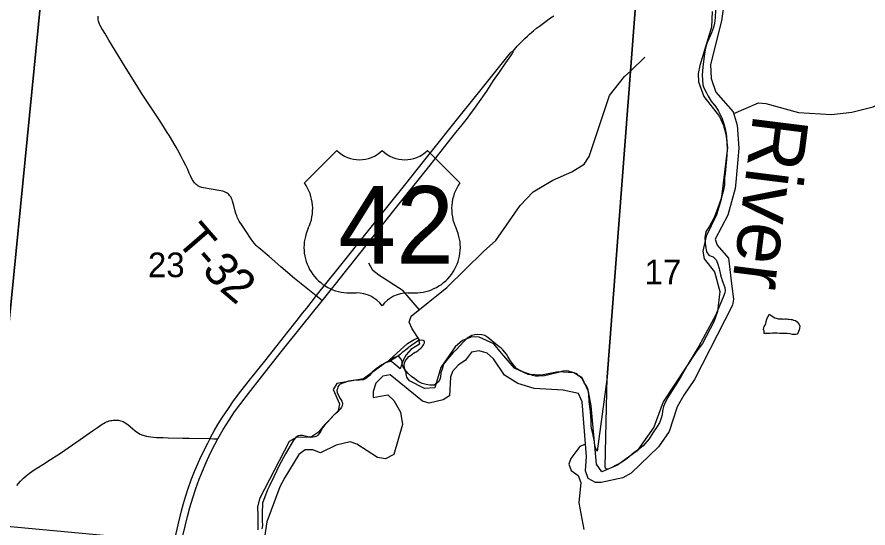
# Model space of a CAD drawing. Extents: x -19.5 to 44.1, y 0 to 22.
# Drawn here: x -17.865 to -16.421, y 14.832 to 15.7 of the extents above; entities that cross this region are included whole.
import ezdxf

# ---------------------------------------------------------------- set-up
doc = ezdxf.new("R2010")
doc.units = 0
for name, color, linetype in [('GM_X_Major_River', 7, 'Continuous'), ('GM_X_Major_River_Text', 7, 'Continuous'), ('GM_X_Minor_Lake', 7, 'Continuous'), ('GM_X_Minor_River', 7, 'Continuous'), ('GM_X_Section', 7, 'Continuous'), ('GM_X_Section_Text', 7, 'Continuous'), ('GM_X_Township_Road', 7, 'Continuous'), ('GM_X_Township_Road_Text', 7, 'Continuous'), ('GM_X_US_Location', 7, 'Continuous'), ('GM_X_US_Route', 7, 'Continuous'), ('GM_X_US_Shield', 7, 'Continuous')]:
    doc.layers.add(name, color=color, linetype=linetype)

msp = doc.modelspace()

# ---------------------------------------------------------------- linework, layer by layer
at = {"layer": 'GM_X_Major_River'}
for points in [[(-16.6661, 15.717), (-16.6691, 15.6932), (-16.6878, 15.6192), (-16.6867, 15.5953), (-16.6787, 15.5718), (-16.6493, 15.5389), (-16.6425, 15.5159), (-16.6399, 15.4767), (-16.6452, 15.4194), (-16.6463, 15.4084), (-16.6584, 15.3632), (-16.6798, 15.3224), (-16.6767, 15.3124), (-16.6573, 15.2898), (-16.652, 15.2421), (-16.6489, 15.2203), (-16.6508, 15.2105), (-16.7152, 15.084)], [(-16.6853, 15.7093), (-16.6862, 15.6823), (-16.7061, 15.6175), (-16.7088, 15.6036), (-16.7081, 15.5895), (-16.6991, 15.5649), (-16.6728, 15.5306), (-16.6657, 15.5155), (-16.662, 15.5006), (-16.6589, 15.478), (-16.6701, 15.3898), (-16.6778, 15.3638), (-16.6956, 15.3275), (-16.701, 15.3022), (-16.6988, 15.2892), (-16.6813, 15.2666), (-16.6724, 15.2336), (-16.6762, 15.1995), (-16.6821, 15.1822), (-16.7015, 15.1452), (-16.711, 15.1325), (-16.7681, 15.0461), (-16.7839, 15.0033), (-16.8126, 14.9631), (-16.8456, 14.9383), (-16.8722, 14.927), (-16.8813, 14.9402), (-16.8903, 15.0394), (-16.8948, 15.0635)], [(-17.2033, 15.0879), (-17.2042, 15.0936), (-17.2046, 15.0966), (-17.206, 15.0993), (-17.2071, 15.1046), (-17.2079, 15.1077), (-17.207, 15.1119), (-17.2059, 15.1149), (-17.2047, 15.1172), (-17.202, 15.1202), (-17.2001, 15.1228), (-17.197, 15.125), (-17.1939, 15.1269), (-17.192, 15.1288), (-17.1893, 15.1303), (-17.1874, 15.131), (-17.1848, 15.1325), (-17.1825, 15.1347), (-17.1794, 15.137), (-17.1775, 15.1392), (-17.1748, 15.143), (-17.1732, 15.146), (-17.1732, 15.1483), (-17.1754, 15.1502), (-17.1785, 15.1507), (-17.1815, 15.1503), (-17.1838, 15.1496), (-17.1869, 15.1477), (-17.1896, 15.1459), (-17.1915, 15.1444), (-17.1941, 15.1429), (-17.1976, 15.1403), (-17.201, 15.1384), (-17.2026, 15.1361), (-17.2049, 15.1343), (-17.208, 15.1324), (-17.211, 15.1298), (-17.2145, 15.1264), (-17.2168, 15.1249), (-17.2191, 15.1234), (-17.221, 15.1219), (-17.2237, 15.1201), (-17.2264, 15.1186), (-17.2298, 15.1163), (-17.2317, 15.1145), (-17.2398, 15.1121)], [(-17.2328, 15.1172), (-17.2024, 15.1451), (-17.1909, 15.152), (-17.184, 15.1549), (-17.1816, 15.1439), (-17.1966, 15.1351), (-17.2043, 15.1261), (-17.209, 15.1182), (-17.2144, 15.1021)], [(-16.8948, 15.0635), (-16.9055, 15.0866), (-16.9197, 15.0951), (-16.9466, 15.0971), (-16.9749, 15.0911), (-16.9976, 15.0926), (-17.0205, 15.1032), (-17.0425, 15.1286), (-17.0556, 15.1443), (-17.0803, 15.1561), (-17.0932, 15.1565), (-17.1086, 15.1501), (-17.1215, 15.1395), (-17.1458, 15.1042), (-17.1557, 15.0699), (-17.1732, 15.0689), (-17.1986, 15.0819), (-17.2033, 15.0879)], [(-16.7152, 15.084), (-16.7332, 15.0572), (-16.7448, 15.0374), (-16.7583, 14.9956), (-16.7763, 14.9696), (-16.8225, 14.9247), (-16.8365, 14.9168), (-16.8736, 14.9088), (-16.8831, 14.9091), (-16.8954, 14.9156), (-16.9003, 14.929), (-16.8984, 14.9533), (-16.9057, 15.0459), (-16.912, 15.0602), (-16.9381, 15.0656), (-16.9874, 15.0687), (-17.0148, 15.0772), (-17.0376, 15.0912), (-17.0561, 15.1192), (-17.0671, 15.129), (-17.0807, 15.1325), (-17.0933, 15.1306), (-17.104, 15.1169), (-17.1164, 15.1082), (-17.1259, 15.0978), (-17.1292, 15.088), (-17.131, 15.0565), (-17.1419, 15.0497), (-17.1652, 15.0436), (-17.1769, 15.0473), (-17.2317, 15.0917), (-17.2443, 15.0898), (-17.2557, 15.0776), (-17.2603, 15.0637), (-17.2603, 15.0534), (-17.2355, 15.058), (-17.2255, 15.0485), (-17.214, 15.0287), (-17.2105, 15.0073), (-17.2254, 14.9565), (-17.2397, 14.9493), (-17.2533, 14.9517), (-17.2883, 14.9741), (-17.2996, 14.9779), (-17.3233, 14.9725), (-17.3496, 14.9593), (-17.3627, 14.9643), (-17.3756, 14.9643), (-17.3865, 14.9567), (-17.4106, 14.9175), (-17.4187, 14.9018), (-17.4411, 14.842), (-17.4478, 14.7978)], [(-17.2398, 15.1121), (-17.2771, 15.0851), (-17.3222, 15.0771), (-17.3283, 15.067), (-17.3176, 15.0427), (-17.3199, 15.031), (-17.3427, 15.0074), (-17.3534, 14.9944), (-17.367, 14.9857), (-17.3901, 14.9861), (-17.4029, 14.9789), (-17.4531, 14.8812), (-17.4566, 14.8673), (-17.4559, 14.8532), (-17.456, 14.8284)], [(-17.2144, 15.1021), (-17.2328, 15.1172)]]:
    msp.add_lwpolyline(points, dxfattribs=at)
at = {"layer": 'GM_X_Minor_Lake'}
msp.add_lwpolyline([(-16.5881, 15.1948), (-16.5865, 15.1938), (-16.5838, 15.1922), (-16.5819, 15.1907), (-16.5789, 15.1888), (-16.5763, 15.188), (-16.5732, 15.1872), (-16.5694, 15.1871), (-16.566, 15.1871), (-16.5641, 15.1867), (-16.5618, 15.187), (-16.5592, 15.187), (-16.5565, 15.1866), (-16.5542, 15.1865), (-16.5512, 15.1857), (-16.5493, 15.1857), (-16.547, 15.1846), (-16.544, 15.1841), (-16.541, 15.1822), (-16.5376, 15.1776), (-16.5365, 15.1745), (-16.5369, 15.1711), (-16.5377, 15.1685), (-16.5389, 15.1658), (-16.5397, 15.1628), (-16.5405, 15.1609), (-16.5424, 15.1602), (-16.5443, 15.1602), (-16.5462, 15.1602), (-16.5488, 15.1606), (-16.5526, 15.1614), (-16.5576, 15.1619), (-16.5648, 15.162), (-16.5705, 15.1624), (-16.575, 15.1629), (-16.5785, 15.1625), (-16.5804, 15.1625), (-16.583, 15.1626), (-16.5865, 15.1622), (-16.5895, 15.1623), (-16.5918, 15.1623), (-16.5937, 15.162), (-16.5971, 15.162), (-16.597, 15.1662), (-16.5978, 15.1688), (-16.5977, 15.1719), (-16.597, 15.1738), (-16.5954, 15.176), (-16.5939, 15.1791), (-16.5934, 15.1825), (-16.5923, 15.1863), (-16.5883, 15.1949)], dxfattribs=at)
at = {"layer": 'GM_X_Minor_River'}
for points in [[(-17.1814, 15.1503), (-17.194, 15.1703), (-17.1991, 15.1815), (-17.1962, 15.1917), (-17.1357, 15.2401), (-17.0734, 15.3015), (-17.0522, 15.32), (-17.0108, 15.3796), (-16.9887, 15.4027), (-16.9557, 15.4228), (-16.9231, 15.4366), (-16.9024, 15.4498), (-16.8938, 15.4626), (-16.8591, 15.5663), (-16.8342, 15.5988), (-16.8234, 15.6081), (-16.7994, 15.6315)], [(-16.6485, 15.5359), (-16.6063, 15.5537), (-16.5938, 15.5526), (-16.5387, 15.5374), (-16.4829, 15.5343), (-16.4483, 15.5381), (-16.4121, 15.5472), (-16.3125, 15.5949), (-16.3029, 15.5992), (-16.1433, 15.5563), (-16.1041, 15.5433), (-16.0813, 15.5436), (-16.0065, 15.5818), (-15.9738, 15.5891), (-15.9377, 15.6089)], [(-17.1825, 15.2027), (-17.2094, 15.2345), (-17.251, 15.2612), (-17.2611, 15.2694), (-17.2677, 15.2814)], [(-16.9, 14.9744), (-16.9099, 14.9701), (-16.9251, 14.9499), (-16.9283, 14.9401), (-16.9243, 14.9297), (-16.9127, 14.9211), (-16.908, 14.9093), (-16.9114, 14.8747), (-16.9031, 14.8294)]]:
    msp.add_lwpolyline(points, dxfattribs=at)
at = {"layer": 'GM_X_Section'}
msp.add_lwpolyline([(-18.8417, 15.9351), (-17.8129, 15.843), (-17.9125, 14.8374), (-18.924, 14.9235)], close=True, dxfattribs=at)
for points in [[(-17.5783, 14.8063), (-17.9125, 14.8374), (-17.8129, 15.843)], [(-16.8129, 15.7495), (-16.8634, 15.0877), (-16.8804, 14.9623), (-16.8826, 14.9665), (-16.884, 14.9718), (-16.885, 14.9779), (-16.8857, 14.9836), (-16.8864, 14.9862), (-16.8878, 14.9923), (-16.8892, 14.9984), (-16.8903, 15.0045), (-16.8905, 15.014), (-16.8917, 15.0303), (-16.8941, 15.0462), (-16.8946, 15.0587), (-16.8956, 15.0659), (-16.8967, 15.0697), (-16.8985, 15.0732), (-16.9004, 15.0762), (-16.9022, 15.0782), (-16.9033, 15.0808), (-16.9052, 15.0846), (-16.9096, 15.0893), (-16.9119, 15.0904), (-16.9137, 15.0924), (-16.9163, 15.0943), (-16.9194, 15.0955), (-16.9258, 15.0971), (-16.9291, 15.0983), (-16.9322, 15.0987), (-16.9386, 15.0981), (-16.9489, 15.0956), (-16.9626, 15.0917), (-16.9698, 15.0903), (-16.9797, 15.0897), (-16.985, 15.0898), (-16.9899, 15.091), (-16.9932, 15.0926), (-17, 15.0946), (-17.0064, 15.097), (-17.012, 15.1001), (-17.0173, 15.1029), (-17.0206, 15.1067), (-17.0243, 15.1117), (-17.0284, 15.1175), (-17.0317, 15.1232), (-17.0339, 15.127), (-17.0402, 15.1343), (-17.0432, 15.137), (-17.0466, 15.1397), (-17.0526, 15.1444), (-17.0593, 15.1494), (-17.066, 15.1552), (-17.0709, 15.1587), (-17.0761, 15.1599), (-17.0829, 15.1604), (-17.0879, 15.1601), (-17.0932, 15.1587), (-17.1016, 15.1539), (-17.1066, 15.1483), (-17.1132, 15.1409), (-17.119, 15.1349), (-17.1248, 15.1301), (-17.1344, 15.1185), (-17.141, 15.1099), (-17.1434, 15.1017), (-17.1454, 15.0956), (-17.1459, 15.0881), (-17.1471, 15.0839), (-17.1495, 15.0802), (-17.1545, 15.0761), (-17.1571, 15.0746), (-17.1598, 15.0743), (-17.164, 15.0744), (-17.1704, 15.0756), (-17.1775, 15.0773), (-17.1843, 15.0804), (-17.1899, 15.085), (-17.1955, 15.0889), (-17.2011, 15.0943), (-17.2067, 15.1012), (-17.21, 15.1066), (-17.2111, 15.1096), (-17.2113, 15.1153), (-17.2135, 15.1192), (-17.2158, 15.1218), (-17.2188, 15.1234), (-17.2245, 15.1212), (-17.2337, 15.1157), (-17.2459, 15.1087), (-17.2555, 15.1021), (-17.262, 15.0965), (-17.2667, 15.0909), (-17.2713, 15.0868), (-17.2744, 15.0846), (-17.2774, 15.0835), (-17.2839, 15.0829), (-17.2945, 15.0823), (-17.3021, 15.0813), (-17.3104, 15.0784), (-17.3165, 15.0759), (-17.3188, 15.074), (-17.3204, 15.0714), (-17.3212, 15.0684), (-17.322, 15.0657), (-17.3213, 15.062), (-17.3199, 15.0581), (-17.3166, 15.052), (-17.3136, 15.0474), (-17.3126, 15.044), (-17.313, 15.0395), (-17.3142, 15.0372), (-17.3165, 15.0335), (-17.3211, 15.0286), (-17.3269, 15.0238), (-17.3385, 15.0107), (-17.3435, 15.0052), (-17.347, 15.0011), (-17.3494, 14.9962), (-17.3521, 14.9921), (-17.3544, 14.9894), (-17.3563, 14.9876), (-17.3597, 14.9865), (-17.3624, 14.9862), (-17.3692, 14.9863), (-17.3756, 14.9879), (-17.3802, 14.9888), (-17.3843, 14.9888), (-17.3877, 14.9881), (-17.3916, 14.9855), (-17.3954, 14.9807), (-17.4036, 14.9676), (-17.4095, 14.9578), (-17.4197, 14.9379), (-17.4291, 14.9188), (-17.4362, 14.9034), (-17.4397, 14.8966), (-17.4433, 14.8878), (-17.446, 14.8801), (-17.448, 14.8741), (-17.4485, 14.8691), (-17.449, 14.8616), (-17.4486, 14.8442), (-17.4483, 14.8362), (-17.4492, 14.8301)], [(-16.6795, 15.712), (-16.6798, 15.6983), (-16.6811, 15.6893), (-16.6831, 15.6821), (-16.6863, 15.6727), (-16.6906, 15.6626), (-16.6934, 15.6562), (-16.6966, 15.6471), (-16.6987, 15.6332), (-16.7009, 15.6143), (-16.7019, 15.6014), (-16.7017, 15.5931), (-16.7007, 15.5847), (-16.6993, 15.5794), (-16.6956, 15.5721), (-16.6919, 15.5653), (-16.6868, 15.5568), (-16.679, 15.5469), (-16.6742, 15.5396), (-16.6687, 15.5285), (-16.6651, 15.5182), (-16.6623, 15.5072), (-16.6609, 15.4969), (-16.66, 15.4859), (-16.6598, 15.4761), (-16.66, 15.4647), (-16.6628, 15.4341), (-16.6641, 15.4266), (-16.6643, 15.4148), (-16.6659, 15.4054), (-16.6676, 15.3994), (-16.6704, 15.3896), (-16.6756, 15.3753), (-16.6811, 15.3602), (-16.6897, 15.3445), (-16.6952, 15.3358), (-16.6964, 15.3321), (-16.6972, 15.3283), (-16.6976, 15.3253), (-16.697, 15.3158), (-16.696, 15.3075), (-16.6946, 15.301), (-16.6906, 15.2952), (-16.6868, 15.2933), (-16.6834, 15.2925), (-16.6786, 15.2875), (-16.676, 15.2814), (-16.6732, 15.2726), (-16.6711, 15.2616), (-16.6682, 15.2521), (-16.6639, 15.2403), (-16.6632, 15.2346), (-16.6637, 15.2312), (-16.6665, 15.2236), (-16.6708, 15.2131), (-16.6795, 15.1928), (-16.6932, 15.1677), (-16.708, 15.1407), (-16.7182, 15.1238), (-16.7244, 15.1133), (-16.7377, 15.0897), (-16.7478, 15.0732), (-16.7533, 15.0653), (-16.7587, 15.0563), (-16.7642, 15.0462), (-16.7678, 15.0379), (-16.7694, 15.03), (-16.7699, 15.024), (-16.7715, 15.0183), (-16.7747, 15.0104), (-16.7797, 15.0022), (-16.7856, 14.9932), (-16.7922, 14.9835), (-16.8022, 14.9715), (-16.8103, 14.9652), (-16.8183, 14.9593), (-16.8295, 14.95), (-16.8372, 14.9441), (-16.8459, 14.9397), (-16.8574, 14.9335), (-16.8621, 14.9315), (-16.8654, 14.9321), (-16.8665, 14.9353), (-16.8634, 15.0877), (-16.8129, 15.7495)]]:
    msp.add_lwpolyline(points, dxfattribs=at)
at = {"layer": 'GM_X_Township_Road'}
for points in [[(-17.3571, 15.2259), (-17.3884, 15.2511), (-17.3938, 15.2555), (-17.417, 15.2754), (-17.4372, 15.2927), (-17.4547, 15.3076), (-17.4572, 15.3099), (-17.4592, 15.3118), (-17.4624, 15.3155), (-17.4675, 15.3224), (-17.4761, 15.3353), (-17.483, 15.3457), (-17.4877, 15.3529), (-17.49, 15.3572), (-17.4911, 15.3596), (-17.4921, 15.3622), (-17.4934, 15.3662), (-17.4945, 15.3698), (-17.4969, 15.3793), (-17.499, 15.3871), (-17.4997, 15.3892), (-17.5006, 15.3913), (-17.5014, 15.3929), (-17.5022, 15.3941), (-17.5031, 15.3955), (-17.5041, 15.3967), (-17.5054, 15.3981), (-17.5067, 15.3993), (-17.5081, 15.4003), (-17.5095, 15.4012), (-17.5118, 15.4024), (-17.5141, 15.4032), (-17.5164, 15.4039), (-17.5191, 15.4044), (-17.5351, 15.407), (-17.5485, 15.4094), (-17.551, 15.41), (-17.5531, 15.4106), (-17.5549, 15.4113), (-17.5564, 15.4121), (-17.558, 15.4131), (-17.5594, 15.4141), (-17.5608, 15.4152), (-17.5621, 15.4164), (-17.5634, 15.418), (-17.5648, 15.4197), (-17.5661, 15.4216), (-17.5674, 15.4237), (-17.5705, 15.4298), (-17.5726, 15.4347), (-17.5752, 15.4405), (-17.5785, 15.4472), (-17.583, 15.456), (-17.5864, 15.4628), (-17.592, 15.4733), (-17.5948, 15.4788), (-17.5962, 15.4815), (-17.6062, 15.4979), (-17.6098, 15.5037), (-17.6192, 15.5183), (-17.6254, 15.5276), (-17.6288, 15.5328), (-17.6401, 15.5498), (-17.6538, 15.5705), (-17.6616, 15.5832), (-17.6796, 15.6122), (-17.6982, 15.6429), (-17.7088, 15.6604), (-17.7161, 15.672), (-17.7212, 15.6804), (-17.7238, 15.6853), (-17.7248, 15.6874), (-17.7255, 15.6892), (-17.726, 15.691), (-17.7265, 15.6927), (-17.7269, 15.6948), (-17.7271, 15.6968), (-17.7273, 15.7011)], [(-17.347, 15.2177), (-17.3492, 15.2196), (-17.3571, 15.2259)], [(-17.8653, 14.9039), (-17.8625, 14.9072), (-17.8587, 14.9113), (-17.854, 14.9163), (-17.8493, 14.9205), (-17.8439, 14.9248), (-17.8356, 14.9303), (-17.8209, 14.9397), (-17.8079, 14.9481), (-17.7913, 14.959), (-17.7575, 14.9821), (-17.7368, 14.9966), (-17.7281, 15.0026), (-17.7205, 15.008), (-17.718, 15.0095), (-17.7155, 15.0108), (-17.7132, 15.0119), (-17.7109, 15.0128), (-17.7084, 15.0136), (-17.706, 15.0142), (-17.7039, 15.0146), (-17.7016, 15.0149), (-17.6994, 15.0151), (-17.6972, 15.0151), (-17.6951, 15.015), (-17.6927, 15.0148), (-17.6907, 15.0144), (-17.6884, 15.0138), (-17.6866, 15.0133), (-17.6848, 15.0125), (-17.6832, 15.0117), (-17.6814, 15.0106), (-17.6768, 15.0073), (-17.6682, 15.0001), (-17.6646, 14.9969)], [(-17.6646, 14.9969), (-17.6643, 14.9966), (-17.6604, 14.9938), (-17.6557, 14.9911), (-17.6512, 14.9893), (-17.6453, 14.9877), (-17.6417, 14.987), (-17.6375, 14.9864), (-17.6332, 14.986), (-17.6283, 14.9857), (-17.6253, 14.9856), (-17.6166, 14.9853), (-17.6086, 14.9852), (-17.5833, 14.9846), (-17.5728, 14.9844), (-17.5373, 14.9836)], [(-17.5373, 14.9836), (-17.5307, 14.9835), (-17.524, 14.9833)]]:
    msp.add_lwpolyline(points, dxfattribs=at)
at = {"layer": 'GM_X_US_Route'}
for points in [[(-17.0229, 15.6417), (-17.0158, 15.65), (-17.0119, 15.6541), (-17.0081, 15.6581), (-17.003, 15.6632), (-16.9985, 15.6674), (-16.9952, 15.6703), (-16.9911, 15.674), (-16.9882, 15.6764), (-16.9832, 15.6805), (-16.9782, 15.6844), (-16.9668, 15.6927), (-16.9595, 15.6982), (-16.9539, 15.7018)], [(-17.612, 14.7484), (-17.5914, 14.8374), (-17.5857, 14.8609), (-17.5824, 14.8735), (-17.579, 14.8848), (-17.5744, 14.899), (-17.5692, 14.9136), (-17.5635, 14.928), (-17.5587, 14.9394), (-17.5528, 14.9524), (-17.5413, 14.9758), (-17.5373, 14.9836), (-17.5357, 14.9869), (-17.5304, 14.9967), (-17.5242, 15.0074), (-17.5163, 15.02), (-17.5062, 15.035), (-17.4973, 15.0477), (-17.485, 15.0641), (-17.4705, 15.0826), (-17.4423, 15.1182), (-17.4067, 15.1629), (-17.3895, 15.1849), (-17.3801, 15.1965), (-17.3731, 15.2053), (-17.3602, 15.222), (-17.3571, 15.2259), (-17.3197, 15.2723), (-17.2659, 15.3399), (-17.2303, 15.3847), (-17.2051, 15.4163), (-17.1882, 15.4377), (-17.168, 15.463), (-17.1122, 15.5329), (-17.0751, 15.5796), (-17.0435, 15.6188), (-17.0276, 15.6386), (-17.0267, 15.6396), (-17.0258, 15.6404), (-17.0248, 15.641), (-17.0239, 15.6414), (-17.0229, 15.6417)], [(-17.0964, 15.5336), (-17.087, 15.5464), (-17.0773, 15.5599), (-17.0678, 15.574), (-17.056, 15.5916), (-17.0463, 15.6059), (-17.0351, 15.6221), (-17.0271, 15.6339), (-17.0248, 15.6369), (-17.0238, 15.6383), (-17.0233, 15.6392), (-17.0231, 15.6398), (-17.023, 15.6403), (-17.0229, 15.6409), (-17.0229, 15.6417)], [(-17.5832, 14.8184), (-17.5754, 14.8511), (-17.5713, 14.8667), (-17.5665, 14.8828), (-17.5612, 14.8988), (-17.5555, 14.9146), (-17.5501, 14.9285), (-17.5439, 14.9428), (-17.5369, 14.9581), (-17.5292, 14.9737), (-17.524, 14.9833), (-17.5219, 14.9874), (-17.5149, 14.9992), (-17.5049, 15.015), (-17.4955, 15.0289), (-17.4853, 15.043), (-17.4721, 15.0604), (-17.4498, 15.0887), (-17.4163, 15.1311), (-17.3799, 15.1767), (-17.3495, 15.2145), (-17.347, 15.2177), (-17.3245, 15.2462), (-17.3075, 15.2677), (-17.2807, 15.3011), (-17.2255, 15.3708), (-17.1639, 15.448), (-17.1199, 15.5034), (-17.1117, 15.5136), (-17.1004, 15.5281), (-17.0964, 15.5336)]]:
    msp.add_lwpolyline(points, dxfattribs=at)
at = {"layer": 'GM_X_US_Shield'}
for p, q in [((-17.3221, 15.473), (-17.377, 15.418)), ((-17.1134, 15.418), (-17.1683, 15.473)), ((-17.3001, 15.2313), (-17.2891, 15.2313)), ((-17.2012, 15.2313), (-17.1903, 15.2313))]:
    msp.add_line(p, q, dxfattribs=at)
for centre, radius, start, end in [((-17.2836, 15.5122), 0.0549, 225.573, 314.427), ((-17.2067, 15.5122), 0.0549, 225.573, 314.427), ((-17.44, 15.3739), 0.0769, 334.5471, 35.0009), ((-17.0504, 15.3739), 0.0769, 144.9991, 205.4529), ((-17.301, 15.3082), 0.0769, 154.8319, 270.6383), ((-17.1894, 15.3082), 0.0769, 269.3617, 25.1681), ((-17.2891, 15.1763), 0.0549, 36.8699, 90), ((-17.2012, 15.1763), 0.0549, 90, 143.1301)]:
    msp.add_arc(centre, radius, start, end, dxfattribs=at)

# ---------------------------------------------------------------- texts
at = {"layer": 'GM_X_Major_River_Text'}
msp.add_text('River', height=0.09468, rotation=262.8673, dxfattribs=at).set_placement((-16.6149, 15.5367))
at = {"layer": 'GM_X_Section_Text'}
for s, p in [('23', (-17.6427, 15.2578)), ('17', (-16.7998, 15.2458))]:
    msp.add_text(s, height=0.04186, rotation=0, dxfattribs=at).set_placement(p)
at = {"layer": 'GM_X_Township_Road_Text'}
for s, rotation, p in [('T', 310.8948, (-17.5964, 15.319)), ('-', 310.9319, (-17.5686, 15.2869)), ('3', 311.9703, (-17.5525, 15.2684)), ('2', 319.8178, (-17.523, 15.2365))]:
    msp.add_text(s, height=0.0568, rotation=rotation, dxfattribs=at).set_placement(p)
at = {"layer": 'GM_X_US_Location'}
for s in ['/', '0']:
    msp.add_text(s, height=0.000189, dxfattribs=at).set_placement((-17.2453, 15.3456))
msp.add_text('42', height=0.000189, rotation=0, dxfattribs=at).set_placement((-17.2844, 15.3064))
at = {"layer": 'GM_X_US_Shield'}
msp.add_text('42', height=0.13184, dxfattribs=at).set_placement((-17.3194, 15.2807))

doc.saveas('drawing.dxf')
